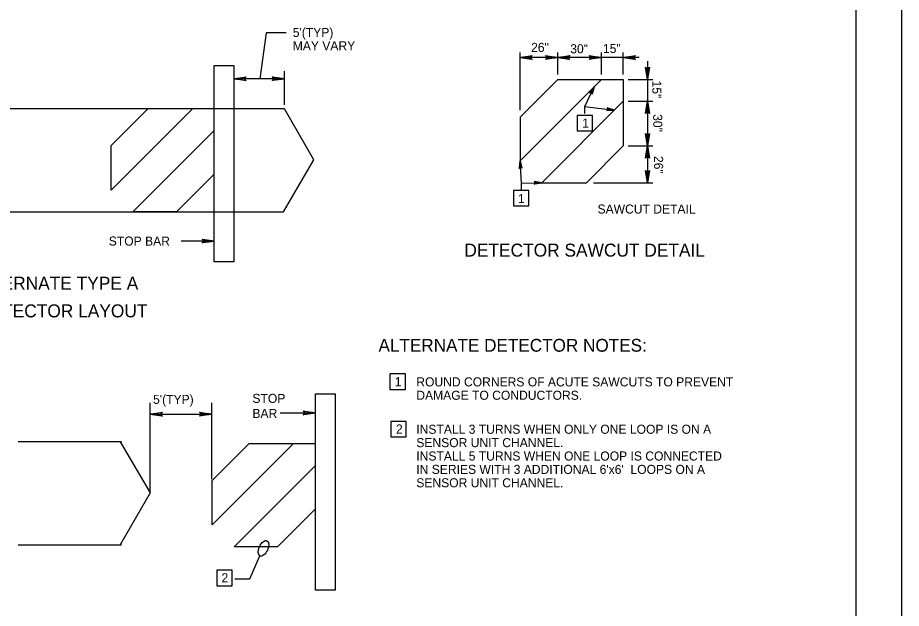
# Model space of a CAD drawing. Extents: x 2709 to 3899, y 22 to 1210.
# Drawn here: x 3256.6 to 3549.9, y 886.9 to 1083 of the extents above; entities that cross this region are included whole.
import ezdxf

# ---------------------------------------------------------------- set-up
doc = ezdxf.new("R2010")
doc.units = 0
for name, color, linetype in [('1', 7, 'Continuous'), ('15', 7, 'Continuous'), ('16', 7, 'Continuous'), ('17', 7, 'Continuous'), ('PLT-BNDY', 7, 'Continuous')]:
    doc.layers.add(name, color=color, linetype=linetype)

msp = doc.modelspace()

# ---------------------------------------------------------------- linework, layer by layer
at = {"layer": '1'}
for p, q in [((3534.86, 631.17), (3534.86, 1195.17)), ((3338.99, 1077.98), (3336.92, 1062.71))]:
    msp.add_line(p, q, dxfattribs=at)
for points in [[(3427.15, 1069.24), (3427.01, 1069.52), (3423.29, 1069.72), (3427.15, 1069.24), (3427.35, 1069.07), (3423.29, 1069.72), (3427, 1069.91), (3427.14, 1070.18), (3423.29, 1069.72), (3427.35, 1070.37), (3427.14, 1070.18)], [(3431.97, 1070.21), (3432.11, 1069.93), (3435.83, 1069.72), (3431.97, 1070.21), (3431.77, 1070.38), (3435.83, 1069.72), (3432.11, 1069.54), (3431.98, 1069.26), (3435.83, 1069.72), (3431.77, 1069.08), (3431.98, 1069.26)], [(3439.69, 1069.24), (3439.54, 1069.52), (3435.83, 1069.72), (3439.69, 1069.24), (3439.88, 1069.07), (3435.83, 1069.72), (3439.54, 1069.91), (3439.68, 1070.18), (3435.83, 1069.72), (3439.88, 1070.37), (3439.68, 1070.18)], [(3446.43, 1070.21), (3446.58, 1069.93), (3450.29, 1069.72), (3446.43, 1070.21), (3446.23, 1070.38), (3450.29, 1069.72), (3446.58, 1069.54), (3446.44, 1069.26), (3450.29, 1069.72), (3446.23, 1069.08), (3446.44, 1069.26)], [(3461.38, 1069.24), (3461.24, 1069.52), (3457.52, 1069.72), (3461.38, 1069.24), (3461.58, 1069.07), (3457.52, 1069.72), (3461.24, 1069.91), (3461.37, 1070.18), (3457.52, 1069.72), (3461.58, 1070.37), (3461.37, 1070.18)], [(3466.11, 1066.3), (3465.83, 1066.16), (3465.62, 1062.44), (3466.11, 1066.3), (3466.28, 1066.5), (3465.62, 1062.44), (3465.44, 1066.16), (3465.16, 1066.29), (3465.62, 1062.44), (3464.98, 1066.5), (3465.16, 1066.29)], [(3332.15, 1062.23), (3332.01, 1062.51), (3328.29, 1062.71), (3332.15, 1062.23), (3332.35, 1062.06), (3328.29, 1062.71), (3332.01, 1062.89), (3332.14, 1063.17), (3328.29, 1062.71), (3332.35, 1063.36), (3332.14, 1063.17)], [(3341.22, 1063.2), (3341.36, 1062.92), (3345.08, 1062.71), (3341.22, 1063.2), (3341.02, 1063.36), (3345.08, 1062.71), (3341.36, 1062.53), (3341.23, 1062.25), (3345.08, 1062.71), (3341.02, 1062.07), (3341.23, 1062.25)], [(3465.14, 1051.35), (3465.42, 1051.49), (3465.62, 1055.21), (3465.14, 1051.35), (3464.97, 1051.15), (3465.62, 1055.21), (3465.81, 1051.5), (3466.08, 1051.36), (3465.62, 1055.21), (3466.27, 1051.15), (3466.08, 1051.36)], [(3466.11, 1044.29), (3465.83, 1044.14), (3465.62, 1040.43), (3466.11, 1044.29), (3466.28, 1044.48), (3465.62, 1040.43), (3465.44, 1044.14), (3465.16, 1044.28), (3465.62, 1040.43), (3464.98, 1044.48), (3465.16, 1044.28)], [(3465.14, 1036.57), (3465.42, 1036.71), (3465.62, 1040.43), (3465.14, 1036.57), (3464.97, 1036.37), (3465.62, 1040.43), (3465.81, 1036.71), (3466.08, 1036.58), (3465.62, 1040.43), (3466.27, 1036.37), (3466.08, 1036.58)], [(3466.11, 1032.07), (3465.83, 1031.93), (3465.62, 1028.21), (3466.11, 1032.07), (3466.28, 1032.27), (3465.62, 1028.21), (3465.44, 1031.92), (3465.16, 1032.06), (3465.62, 1028.21), (3464.98, 1032.27), (3465.16, 1032.06)], [(3317.94, 1009.32), (3318.09, 1009.04), (3321.8, 1008.84), (3317.94, 1009.32), (3317.75, 1009.49), (3321.8, 1008.84), (3318.09, 1008.65), (3317.96, 1008.38), (3321.8, 1008.84), (3317.75, 1008.19), (3317.96, 1008.38)], [(3304.41, 950.87), (3304.27, 951.15), (3300.55, 951.35), (3304.41, 950.87), (3304.61, 950.7), (3300.55, 951.35), (3304.27, 951.53), (3304.4, 951.81), (3300.55, 951.35), (3304.61, 952), (3304.4, 951.81)], [(3317.11, 951.84), (3317.25, 951.56), (3320.97, 951.35), (3317.11, 951.84), (3316.91, 952), (3320.97, 951.35), (3317.25, 951.17), (3317.12, 950.89), (3320.97, 951.35), (3316.91, 950.71), (3317.12, 950.89)], [(3351.55, 952.26), (3351.7, 951.98), (3355.41, 951.78), (3351.55, 952.26), (3351.35, 952.43), (3355.41, 951.78), (3351.7, 951.59), (3351.56, 951.32), (3355.41, 951.78), (3351.35, 951.13), (3351.56, 951.32)]]:
    msp.add_lwpolyline(points, dxfattribs=at)
at = {"layer": '15'}
for points in [[(3442.21, 1045.4), (3447.35, 1045.4), (3447.35, 1050.52), (3442.21, 1050.52)], [(3421.1, 1020.48), (3426.23, 1020.48), (3426.23, 1025.6), (3421.1, 1025.6)], [(3380.1, 959.59), (3385.24, 959.59), (3385.24, 964.71), (3380.1, 964.71)], [(3380.4, 943.86), (3385.54, 943.86), (3385.54, 948.99), (3380.4, 948.99)], [(3322.62, 894.43), (3327.76, 894.43), (3327.76, 899.55), (3322.62, 899.55)]]:
    msp.add_lwpolyline(points, close=True, dxfattribs=at)
at = {"layer": '16'}
for p, q in [((3345.67, 1077.98), (3338.99, 1077.98)), ((3321.8, 1001.92), (3321.8, 1067.13)), ((3321.8, 1067.13), (3328.29, 1067.13)), ((3328.29, 1067.13), (3328.29, 1001.92)), ((3345.08, 1054.1), (3345.08, 1065.22)), ((3345.08, 1062.71), (3328.29, 1062.71)), ((3435.83, 1062.44), (3423.29, 1049.91)), ((3450.29, 1062.44), (3423.29, 1035.44)), ((3435.83, 1062.44), (3457.52, 1062.44)), ((3457.52, 1062.44), (3457.52, 1040.43)), ((3457.52, 1055.21), (3430.52, 1028.21)), ((3321.8, 1052.71), (3246.97, 1052.71)), ((3314.57, 1052.71), (3287.57, 1025.72)), ((3299.79, 1052.71), (3287.57, 1040.5)), ((3345.08, 1052.71), (3299.79, 1052.71)), ((3354.83, 1035.82), (3345.08, 1052.71)), ((3423.29, 1049.91), (3423.29, 1035.44)), ((3321.8, 1045.48), (3294.8, 1018.48)), ((3287.57, 1025.72), (3287.57, 1040.5)), ((3457.52, 1040.43), (3445.31, 1028.21)), ((3344.82, 1018.48), (3354.83, 1035.82)), ((3321.8, 1031.02), (3309.27, 1018.48)), ((3430.52, 1028.21), (3445.31, 1028.21)), ((3246.97, 1018.48), (3344.82, 1018.48)), ((3309.27, 1018.48), (3294.8, 1018.48)), ((3321.8, 1008.84), (3310.78, 1008.84)), ((3328.29, 1001.92), (3321.8, 1001.92)), ((3355.41, 892.95), (3355.41, 958.15)), ((3355.41, 958.15), (3361.9, 958.15)), ((3361.9, 958.15), (3361.9, 892.95)), ((3290.97, 942.19), (3256.68, 942.19)), ((3290.54, 942.19), (3300.55, 925.3)), ((3348.14, 941.61), (3321.14, 914.61)), ((3333.36, 941.61), (3321.14, 929.39)), ((3333.36, 941.61), (3355.37, 941.61)), ((3355.37, 919.91), (3355.37, 941.61)), ((3355.37, 934.38), (3328.37, 907.38)), ((3321.14, 914.61), (3321.14, 929.39)), ((3300.55, 925.3), (3290.54, 907.96)), ((3355.37, 919.91), (3342.84, 907.38)), ((3256.68, 907.96), (3290.97, 907.96)), ((3342.84, 907.38), (3328.37, 907.38)), ((3361.9, 892.95), (3355.41, 892.95))]:
    msp.add_line(p, q, dxfattribs=at)
at = {"layer": '17'}
for p, q in [((3423.29, 1052.33), (3423.29, 1071.44)), ((3435.83, 1064.16), (3435.83, 1071.44)), ((3450.29, 1064.16), (3450.29, 1071.44)), ((3457.52, 1064.16), (3457.52, 1071.44)), ((3435.83, 1069.72), (3423.29, 1069.72)), ((3450.29, 1069.72), (3435.83, 1069.72)), ((3462.85, 1069.72), (3450.29, 1069.72)), ((3465.62, 1068.57), (3465.62, 1055.21)), ((3459.24, 1062.44), (3467.34, 1062.44)), ((3444.8, 1053.44), (3447.93, 1060.07)), ((3459.24, 1055.21), (3467.34, 1055.21)), ((3465.62, 1055.21), (3465.62, 1040.43)), ((3459.24, 1040.43), (3467.34, 1040.43)), ((3465.62, 1040.43), (3465.62, 1028.21)), ((3423.74, 1028.04), (3423.29, 1035.44)), ((3447.73, 1028.21), (3467.34, 1028.21)), ((3300.55, 925.3), (3300.55, 955.13)), ((3320.97, 929.8), (3320.97, 955.13)), ((3300.55, 951.35), (3320.97, 951.35)), ((3343.64, 951.78), (3355.41, 951.78)), ((3333.58, 896.7), (3336.97, 904.31)), ((3328.62, 896.7), (3333.58, 896.7))]:
    msp.add_line(p, q, dxfattribs=at)
for points in [[(3447.93, 1060.07), (3447.29, 1057.62), (3447.25, 1057.85), (3447.93, 1060.07), (3447.14, 1058.01), (3447.01, 1058.11), (3447.93, 1060.07), (3446.84, 1058.15), (3446.65, 1058.13), (3447.93, 1060.07), (3446.45, 1058.02), (3446.65, 1058.13), (3446.84, 1058.15), (3447.01, 1058.11), (3447.14, 1058.01), (3447.25, 1057.85)], [(3444.8, 1051.15), (3444.8, 1053.44), (3454.62, 1052.3)], [(3454.62, 1052.3), (3452.08, 1052.13), (3452.29, 1052.24), (3454.62, 1052.3), (3452.41, 1052.39), (3452.46, 1052.55), (3454.62, 1052.3), (3452.45, 1052.72), (3452.37, 1052.9), (3454.62, 1052.3), (3452.19, 1053.06), (3452.37, 1052.9), (3452.45, 1052.72), (3452.46, 1052.55), (3452.41, 1052.39), (3452.29, 1052.24)], [(3423.29, 1035.44), (3423.91, 1032.98), (3423.77, 1033.16), (3423.29, 1035.44), (3423.59, 1033.25), (3423.42, 1033.27), (3423.29, 1035.44), (3423.26, 1033.23), (3423.1, 1033.12), (3423.29, 1035.44), (3422.98, 1032.92), (3423.1, 1033.12), (3423.26, 1033.23), (3423.42, 1033.27), (3423.59, 1033.25), (3423.77, 1033.16)], [(3423.74, 1025.76), (3423.74, 1028.04), (3430.52, 1028.21)], [(3430.52, 1028.21), (3428.04, 1027.68), (3428.23, 1027.82), (3430.52, 1028.21), (3428.32, 1027.99), (3428.35, 1028.16), (3430.52, 1028.21), (3428.32, 1028.32), (3428.21, 1028.49), (3430.52, 1028.21), (3428.02, 1028.62), (3428.21, 1028.49), (3428.32, 1028.32), (3428.35, 1028.16), (3428.32, 1027.99), (3428.23, 1027.82)]]:
    msp.add_lwpolyline(points, dxfattribs=at)
msp.add_ellipse((3338.13, 906.85), major_axis=(-1.16, -2.53), ratio=0.511782, dxfattribs=at)
at = {"layer": 'PLT-BNDY'}
msp.add_lwpolyline([(2708.86, 1210.17), (3549.86, 1210.17), (3549.86, 616.17), (2708.86, 616.17)], close=True, dxfattribs=at)

# ---------------------------------------------------------------- texts
at = {"layer": '1'}
for s, p in [('1', (3443.93, 1046.49)), ('1', (3422.61, 1021.42)), ('1', (3381.72, 960.66)), ('2', (3382.12, 944.95)), ('2', (3324.21, 895.57))]:
    msp.add_text(s, height=3, dxfattribs=at).set_placement(p)
at = {"layer": '17'}
for s, height, p in [("5'(TYP)", 3, (3347.86, 1076.58)), ('MAY VARY', 3, (3347.86, 1072.14)), ('26"', 3, (3426.97, 1071.61)), ('30"', 3, (3439.97, 1071.16)), ('15"', 3, (3450.83, 1071.24)), ('SAWCUT DETAIL', 3, (3449.02, 1017.96)), ('STOP BAR', 3, (3286.8, 1007.33)), ('DETECTOR SAWCUT DETAIL', 4.3, (3404.82, 1003.67)), ('ALTERNATE TYPE A', 4.3, (3240.67, 992.7)), ('DETECTOR LAYOUT', 4.3, (3243.4, 983.51)), ('ALTERNATE DETECTOR NOTES:', 4.25, (3376.32, 972.11)), ('ROUND CORNERS OF ACUTE SAWCUTS TO PREVENT', 3, (3388.87, 960.59)), ('DAMAGE TO CONDUCTORS.', 3, (3388.87, 956.15)), ("5'(TYP)", 3, (3301.5, 954.79)), ('STOP', 3, (3334.47, 955.12)), ('BAR', 3, (3334.47, 950.12)), ('INSTALL 3 TURNS WHEN ONLY ONE LOOP IS ON A ', 3, (3388.87, 944.87)), ('SENSOR UNIT CHANNEL.', 3, (3388.87, 940.43)), ('INSTALL 5 TURNS WHEN ONE LOOP IS CONNECTED', 3, (3388.87, 935.99)), ("IN SERIES WITH 3 ADDITIONAL 6'x6'  LOOPS ON A", 3, (3388.87, 931.55)), ('SENSOR UNIT CHANNEL.', 3, (3388.87, 927.11))]:
    msp.add_text(s, height=height, dxfattribs=at).set_placement(p)
for s, p in [('15"', (3467.2, 1062.09)), ('30"', (3467.5, 1050.94)), ('26"', (3467.8, 1037.07))]:
    msp.add_text(s, height=3, rotation=270, dxfattribs=at).set_placement(p)

doc.saveas('drawing.dxf')
